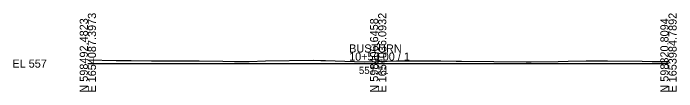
# Model space of a CAD drawing. Extents: x -26 to 1403, y -10 to 2017.
# Drawn here: x -25.7 to 202.8, y 1990.3 to 2017.3 of the extents above; entities that cross this region are included whole.
import ezdxf

# ---------------------------------------------------------------- set-up
doc = ezdxf.new("R2010")
doc.units = 0
for name, color, linetype in [('Exist Cross Section Cell', 7, 'Continuous'), ('Exist XS Center Line Elevation Label', 7, 'Continuous'), ('Exist XS Ground Line', 7, 'Continuous')]:
    doc.layers.add(name, color=color, linetype=linetype)

msp = doc.modelspace()

# ---------------------------------------------------------------- linework, layer by layer
at = {"layer": 'Exist Cross Section Cell'}
for p, q in [((100, 2000), (100, 2003.8)), ((0, 2000), (100, 2000)), ((100, 2000), (200, 2000))]:
    msp.add_line(p, q, dxfattribs=at)
at = {"layer": 'Exist XS Ground Line'}
for p, q in [((0, 2001.27), (9.7, 2001.09)), ((9.7, 2001.09), (14.88, 2001.09)), ((14.88, 2001.09), (21.89, 2000.93)), ((21.89, 2000.93), (34.49, 2001)), ((34.49, 2001), (36.78, 2000.96)), ((36.78, 2000.96), (38.34, 2000.97)), ((38.34, 2000.97), (46.5, 2000.81)), ((46.5, 2000.81), (50.48, 2000.73)), ((50.48, 2000.73), (55.55, 2000.66)), ((55.55, 2000.66), (61.18, 2000.91)), ((61.18, 2000.91), (77.62, 2001.12)), ((77.62, 2001.12), (80.25, 2001.04)), ((80.25, 2001.04), (81.87, 2001.03)), ((81.87, 2001.03), (95.21, 2000.57)), ((95.21, 2000.57), (100, 2000.71)), ((100, 2000.71), (106.34, 2000.9)), ((106.34, 2000.9), (111.41, 2000.91)), ((111.41, 2000.91), (121.53, 2000.89)), ((121.53, 2000.89), (126.87, 2000.8)), ((126.87, 2000.8), (128.17, 2000.81)), ((128.17, 2000.81), (128.73, 2000.83)), ((128.73, 2000.83), (150.94, 2000.58)), ((150.94, 2000.58), (151.65, 2000.58)), ((151.65, 2000.58), (152.65, 2000.57)), ((152.65, 2000.57), (161.98, 2000.69)), ((161.98, 2000.69), (165.5, 2000.8)), ((165.5, 2000.8), (171.66, 2000.9)), ((171.66, 2000.9), (179.02, 2000.95)), ((179.02, 2000.95), (190.99, 2000.86)), ((190.99, 2000.86), (194.37, 2000.74)), ((194.37, 2000.74), (200, 2000.73))]:
    msp.add_line(p, q, dxfattribs=at)

# ---------------------------------------------------------------- texts
at = {"layer": 'Exist Cross Section Cell'}
for s, p in [('E 1654087.3973', (2.8, 1990)), ('E 1654036.0932', (102.8, 1990)), ('E 1653984.7892', (202.8, 1990)), ('N 598492.4823', (0, 1990)), ('N 598406.6458', (100, 1990)), ('N 598320.8094', (200, 1990))]:
    msp.add_text(s, height=2.8, rotation=90, dxfattribs=at).set_placement(p)
for s, p in [('BUSTURN', (90, 2003.8)), ('10+50.00 / 1', (90, 2001)), ('EL 557', (-26, 1998.6))]:
    msp.add_text(s, height=2.8, dxfattribs=at).set_placement(p)
at = {"layer": 'Exist XS Center Line Elevation Label'}
msp.add_text('557.71', height=2.5, dxfattribs=at).set_placement((93.36, 1996.41))

doc.saveas('drawing.dxf')
